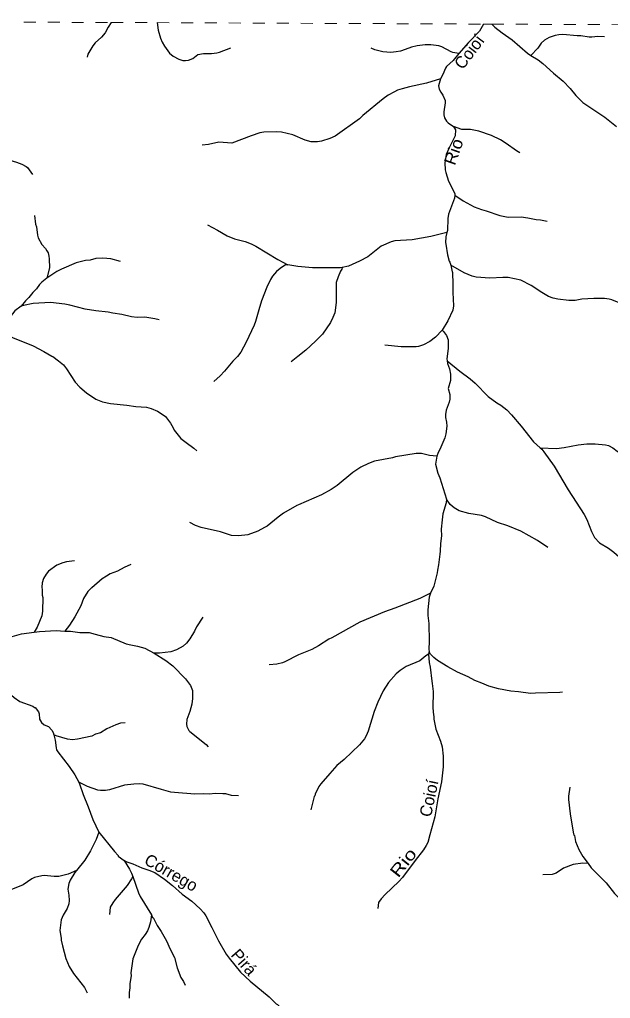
# Model space of a CAD drawing. Extents: x 551.6 to 577.6, y 7567 to 7594.7.
# Drawn here: x 563.65 to 568.58, y 7586.53 to 7594.71 of the extents above; entities that cross this region are included whole.
import ezdxf
from ezdxf.enums import TextEntityAlignment as Align

# ---------------------------------------------------------------- set-up
doc = ezdxf.new("R2010")
doc.units = 0
doc.header["$LTSCALE"] = 0.04
doc.linetypes.add('SHORT_DASHED', pattern=[2.7, 1.5, -1.2])
doc.layers.add('53', color=7, linetype='SHORT_DASHED', lineweight=13)
doc.layers.add('7', color=7, linetype='Continuous', lineweight=25)
doc.layers.add('61', color=7, linetype='Continuous')

msp = doc.modelspace()

# ---------------------------------------------------------------- linework, layer by layer
at = {"layer": '53'}
msp.add_lwpolyline([(557.7663, 7594.7075), (559.9893, 7594.6994), (560.513, 7594.6975), (560.888, 7594.6961), (564.4189, 7594.6832), (564.8007, 7594.6818), (567.5244, 7594.6698), (567.5959, 7594.6695), (570.5848, 7594.6561)], dxfattribs=at)
at = {"layer": '7'}
for points in [[(564.4189, 7594.6832), (564.3936, 7594.6439), (564.3687, 7594.5972), (564.3365, 7594.5602), (564.2842, 7594.5143), (564.2649, 7594.4878), (564.2238, 7594.4185), (564.2166, 7594.3936)], [(564.8007, 7594.6818), (564.8105, 7594.6198), (564.8298, 7594.5522), (564.8443, 7594.5184), (564.8636, 7594.4846), (564.9039, 7594.4282), (564.9361, 7594.4016), (564.9828, 7594.3775), (565.0166, 7594.367), (565.0391, 7594.3654), (565.0633, 7594.3694), (565.0987, 7594.3823), (565.1421, 7594.4153), (565.1872, 7594.4242), (565.2548, 7594.4242), (565.2999, 7594.4298), (565.3224, 7594.4354), (565.4166, 7594.4717)], [(567.5244, 7594.6698), (567.4929, 7594.6101), (567.3988, 7594.5159), (567.3198, 7594.4245)], [(567.5959, 7594.6695), (567.6193, 7594.6455), (567.6813, 7594.5964), (567.765, 7594.5393), (567.8921, 7594.4258), (567.9199, 7594.4085)], [(568.5344, 7594.5634), (568.4788, 7594.565), (568.4289, 7594.5602), (568.4064, 7594.561), (568.3388, 7594.5715), (568.3066, 7594.5707), (568.1875, 7594.5835), (568.1537, 7594.5811), (568.1231, 7594.5739), (568.0748, 7594.5578), (568.0346, 7594.5368), (568.008, 7594.5103), (567.9782, 7594.4692), (567.9199, 7594.4085)], [(567.3198, 7594.4245), (567.2684, 7594.4322), (567.2555, 7594.437), (567.1783, 7594.4789), (567.1525, 7594.4869), (567.0865, 7594.4974), (567.0398, 7594.4974), (566.9722, 7594.4894), (566.924, 7594.4773), (566.8724, 7594.4564), (566.8338, 7594.4451), (566.7968, 7594.437), (566.7517, 7594.4338), (566.6841, 7594.4371), (566.6197, 7594.454), (566.5883, 7594.4701)], [(567.3198, 7594.4245), (567.2716, 7594.3662), (567.2161, 7594.3155), (567.208, 7594.3027), (567.1871, 7594.2487), (567.1654, 7594.2131)], [(567.9199, 7594.4085), (567.9815, 7594.3703), (568.0201, 7594.3405), (568.1102, 7594.2592), (568.1915, 7594.1932), (568.2494, 7594.1329), (568.2961, 7594.0733), (568.3549, 7594.0161), (568.5392, 7593.8922), (568.6349, 7593.8141)], [(567.1654, 7594.2131), (567.0495, 7594.1771), (566.9079, 7594.1473), (566.8451, 7594.1304), (566.8064, 7594.1175), (566.7815, 7594.1055), (566.7308, 7594.0765), (566.6865, 7594.0459), (566.5183, 7593.9067), (566.4894, 7593.8793), (566.2882, 7593.7345), (566.2415, 7593.7135), (566.1739, 7593.691), (566.1385, 7593.6854), (566.087, 7593.6854)], [(567.1654, 7594.2131), (567.1501, 7594.153), (567.1557, 7594.1272), (567.1686, 7594.1015), (567.1863, 7594.0757), (567.2056, 7594.0314), (567.2056, 7594.0129), (567.1943, 7593.9373), (567.1943, 7593.9131), (567.2008, 7593.8874), (567.2177, 7593.8584), (567.2298, 7593.8447), (567.2744, 7593.8145)], [(563.1116, 7593.9131), (563.1172, 7593.8793), (563.1172, 7593.7844), (563.1221, 7593.7618), (563.1454, 7593.7176), (563.1824, 7593.6669), (563.2227, 7593.6298), (563.2637, 7593.6073), (563.3426, 7593.5799), (563.3764, 7593.5719), (563.4472, 7593.5638), (563.5261, 7593.5477), (563.6275, 7593.518), (563.6726, 7593.5003), (563.708, 7593.4818), (563.7192, 7593.4713), (563.7619, 7593.4134)], [(567.2744, 7593.8145), (567.2909, 7593.786), (567.2877, 7593.7361), (567.2386, 7593.6379)], [(567.8293, 7593.5952), (567.8012, 7593.6105), (567.7159, 7593.6741), (567.666, 7593.7031), (567.5911, 7593.7401), (567.4857, 7593.7771), (567.4181, 7593.7892), (567.344, 7593.7892), (567.2744, 7593.8145)], [(566.087, 7593.6854), (566.0355, 7593.7007), (565.934, 7593.7441), (565.8391, 7593.7667), (565.8005, 7593.7715), (565.691, 7593.7667), (565.6572, 7593.761), (565.5864, 7593.7377), (565.4254, 7593.6765), (565.3152, 7593.6838), (565.2307, 7593.6652), (565.1783, 7593.6588)], [(567.2386, 7593.6379), (567.2137, 7593.5816), (567.2024, 7593.5107), (567.2064, 7593.4528), (567.2104, 7593.4303), (567.233, 7593.3594), (567.2853, 7593.2564), (567.286, 7593.2416)], [(567.286, 7593.2416), (567.2845, 7593.2162), (567.233, 7593.0826), (567.2281, 7593.0472), (567.2249, 7592.9474), (567.2201, 7592.9295)], [(567.286, 7593.2416), (567.3569, 7593.1936), (567.4471, 7593.1453), (567.5082, 7593.1204), (567.5485, 7593.1099), (567.6611, 7593.0705), (567.7304, 7593.0568), (567.8398, 7593.06), (567.8961, 7593.0528), (567.9638, 7593.0383), (568.0024, 7593.0359), (568.0579, 7593.023)], [(563.7772, 7593.0721), (563.786, 7592.9989), (563.7933, 7592.9764), (563.8029, 7592.9088), (563.8094, 7592.8862), (563.8391, 7592.8291), (563.8697, 7592.7961), (563.8818, 7592.7768), (563.8914, 7592.7591), (563.8979, 7592.7333), (563.9011, 7592.7108), (563.9027, 7592.6335), (563.8815, 7592.5493)], [(565.221, 7592.9933), (565.3047, 7592.9498), (565.3852, 7592.9031), (565.4479, 7592.8781), (565.5349, 7592.8556), (565.5864, 7592.8363), (565.625, 7592.8162), (565.8085, 7592.7051), (565.8932, 7592.6603)], [(567.2201, 7592.9295), (567.0865, 7592.8975), (566.9288, 7592.8693), (566.7839, 7592.8588), (566.7549, 7592.8524), (566.672, 7592.8154), (566.5602, 7592.726), (566.4902, 7592.689), (566.3992, 7592.6496), (566.346, 7592.6366), (566.3316, 7592.6343)], [(567.2201, 7592.9295), (567.2104, 7592.8927), (567.2072, 7592.846), (567.212, 7592.8331), (567.2249, 7592.743), (567.2386, 7592.6906), (567.2442, 7592.6834), (567.2526, 7592.6566)], [(564.4959, 7592.6874), (564.4162, 7592.7108), (564.347, 7592.7148), (564.2906, 7592.7116), (564.2424, 7592.6995), (564.2037, 7592.6963), (564.1265, 7592.6753), (564.0025, 7592.6238), (563.9639, 7592.6045), (563.8815, 7592.5493)], [(565.8932, 7592.6603), (565.8737, 7592.6608), (565.8278, 7592.6287), (565.798, 7592.6029), (565.7642, 7592.5643), (565.7473, 7592.5369), (565.7159, 7592.4726), (565.6733, 7592.3583), (565.6515, 7592.2842)], [(566.3316, 7592.6343), (566.0982, 7592.6335), (565.9743, 7592.6448), (565.8932, 7592.6603)], [(567.2526, 7592.6566), (567.2627, 7592.6013), (567.2652, 7592.5997), (567.2652, 7592.5579), (567.27, 7592.5369), (567.27, 7592.5192)], [(568.0112, 7592.4275), (567.9243, 7592.4862), (567.8366, 7592.5313), (567.732, 7592.5546), (567.6869, 7592.5546), (567.5791, 7592.5474), (567.4648, 7592.5562), (567.431, 7592.5643), (567.3626, 7592.5916), (567.2526, 7592.6566)], [(566.346, 7592.6366), (566.3429, 7592.6238), (566.3324, 7592.6078), (566.3123, 7592.5595), (566.2962, 7592.5128), (566.2962, 7592.3454), (566.2833, 7592.2601), (566.2688, 7592.2198), (566.2487, 7592.1796), (566.1811, 7592.0822), (566.1224, 7592.0218), (566.0411, 7591.9462), (565.9759, 7591.8939), (565.9188, 7591.8488)], [(563.8815, 7592.5493), (563.8383, 7592.5152), (563.819, 7592.4951), (563.7933, 7592.4597), (563.7627, 7592.4275), (563.7313, 7592.388)], [(567.27, 7592.5192), (567.27, 7592.4291), (567.2748, 7592.3164), (567.2692, 7592.2826), (567.2289, 7592.1909), (567.179, 7592.1138)], [(569.0084, 7591.9599), (568.94, 7592.0259), (568.9118, 7592.0605), (568.8635, 7592.1297), (568.8289, 7592.1973), (568.7959, 7592.24), (568.7195, 7592.3092), (568.6865, 7592.3301), (568.5963, 7592.3663), (568.5754, 7592.3727), (568.5352, 7592.3776), (568.4466, 7592.3792), (568.3468, 7592.3719), (568.2905, 7592.3631), (568.2374, 7592.3631), (568.1456, 7592.3743), (568.107, 7592.3824), (568.0684, 7592.3961), (568.0112, 7592.4275)], [(563.7313, 7592.388), (563.7031, 7592.3599), (563.6652, 7592.314)], [(564.0717, 7592.3228), (564.0315, 7592.3325), (563.9124, 7592.3454), (563.7659, 7592.3373), (563.6854, 7592.3212), (563.6652, 7592.314)], [(564.8178, 7592.2005), (564.7832, 7592.2094), (564.6979, 7592.2239), (564.6351, 7592.2206), (564.5868, 7592.2255), (564.5063, 7592.244), (564.4323, 7592.2552), (564.3937, 7592.2657), (564.289, 7592.2762), (564.2013, 7592.2898), (564.0717, 7592.3228)], [(563.6652, 7592.314), (563.6146, 7592.2746), (563.5623, 7592.2126), (563.5406, 7592.1957), (563.4939, 7592.1651), (563.4193, 7592.1239)], [(565.6515, 7592.2842), (565.6234, 7592.186), (565.6113, 7592.1571), (565.5453, 7592.0154), (565.501, 7591.9317), (565.4729, 7591.8955), (565.4335, 7591.8553), (565.3634, 7591.7708), (565.3272, 7591.7321), (565.2749, 7591.6863)], [(563.4193, 7592.1239), (563.7659, 7591.9824), (563.8569, 7591.9365), (563.922, 7591.8963)], [(567.179, 7592.1138), (567.1252, 7592.0564), (567.0777, 7592.0194), (567.0254, 7591.9913), (566.9819, 7591.9784), (566.9626, 7591.9744), (566.837, 7591.9744), (566.7026, 7591.9881)], [(567.179, 7592.1138), (567.1919, 7592.1023), (567.2177, 7592.0685), (567.2314, 7592.0331), (567.2298, 7591.9607), (567.2201, 7591.8738), (567.2233, 7591.8576)], [(563.922, 7591.8963), (563.9317, 7591.8931), (563.9784, 7591.8593), (564.0186, 7591.8239), (564.046, 7591.7917), (564.1184, 7591.6806), (564.1562, 7591.638), (564.211, 7591.5913), (564.289, 7591.539), (564.3454, 7591.5172), (564.413, 7591.5011), (564.5482, 7591.4875), (564.6222, 7591.4762), (564.7124, 7591.4722), (564.751, 7591.4601)], [(567.2233, 7591.8576), (567.2249, 7591.8352), (567.241, 7591.7901), (567.2507, 7591.7482), (567.2491, 7591.6951), (567.2298, 7591.6275), (567.2442, 7591.576), (567.2434, 7591.5374), (567.2378, 7591.5132), (567.2137, 7591.4456)], [(567.2233, 7591.8576), (567.3272, 7591.7732), (567.4149, 7591.708), (567.4551, 7591.6718), (567.563, 7591.5607), (567.6354, 7591.5076), (567.6692, 7591.4875), (567.7207, 7591.448), (567.7593, 7591.407), (567.839, 7591.312), (567.9428, 7591.1832), (567.9974, 7591.1312)], [(564.751, 7591.4601), (564.8033, 7591.4376), (564.8516, 7591.4086), (564.8701, 7591.3925), (564.9127, 7591.3378), (564.9353, 7591.2975), (564.9421, 7591.2791), (564.9997, 7591.2106), (565.0423, 7591.1752), (565.1075, 7591.1285), (565.1317, 7591.1068)], [(567.2137, 7591.4456), (567.2072, 7591.4102), (567.2072, 7591.3845), (567.2153, 7591.3474), (567.2185, 7591.312), (567.212, 7591.2493), (567.2032, 7591.2155), (567.1702, 7591.1366), (567.1444, 7591.0851), (567.1368, 7591.0621)], [(567.9974, 7591.1312), (568.1344, 7591.1253), (568.1988, 7591.1333), (568.3146, 7591.1559), (568.3871, 7591.1639), (568.4579, 7591.1655), (568.5448, 7591.1575), (568.5698, 7591.1519), (568.6036, 7591.1325), (568.6406, 7591.1028), (568.7404, 7591.0102), (568.7879, 7590.9772), (568.8329, 7590.9539)], [(567.9974, 7591.1312), (568.012, 7591.1205), (568.0297, 7591.0996), (568.115, 7590.9796)], [(567.1368, 7591.0621), (567.0753, 7591.0665), (567.0076, 7591.0834), (566.9626, 7591.0842), (566.792, 7591.0561), (566.7662, 7591.048), (566.6157, 7591.0199), (566.565, 7591.0006), (566.5022, 7590.9708), (566.4354, 7590.9257), (566.3026, 7590.8187), (566.2527, 7590.7849), (566.1723, 7590.7406), (565.9807, 7590.6561)], [(567.1368, 7591.0621), (567.1243, 7590.9949), (567.1444, 7590.9209), (567.1597, 7590.8823), (567.2169, 7590.702)], [(568.115, 7590.9796), (568.2333, 7590.7801), (568.3653, 7590.5764), (568.3879, 7590.533), (568.4257, 7590.4332), (568.4514, 7590.3833), (568.4949, 7590.3382), (568.5673, 7590.2939), (568.614, 7590.2601), (568.7235, 7590.162)], [(567.2169, 7590.702), (567.2128, 7590.673), (567.1863, 7590.5813), (567.179, 7590.5298), (567.1726, 7590.4541), (567.1734, 7590.3962), (567.167, 7590.3334), (567.1646, 7590.269), (567.1597, 7590.2433)], [(568.0627, 7590.3004), (567.9766, 7590.3575), (567.8382, 7590.4372), (567.7271, 7590.4799), (567.6418, 7590.508), (567.542, 7590.5555), (567.5098, 7590.5676), (567.4036, 7590.5845), (567.3215, 7590.607), (567.2797, 7590.6312), (567.2467, 7590.6585), (567.2169, 7590.702)], [(565.9807, 7590.6561), (565.9678, 7590.6513), (565.8567, 7590.5861), (565.8109, 7590.5531), (565.7192, 7590.479), (565.6974, 7590.4654), (565.6427, 7590.4348), (565.5574, 7590.4058), (565.4801, 7590.3978), (565.4222, 7590.401), (565.3304, 7590.43), (565.1679, 7590.4654), (565.1228, 7590.4823), (565.0737, 7590.5072)], [(567.1597, 7590.2433), (567.1509, 7590.1563), (567.1412, 7590.1113), (567.1396, 7590.0887), (567.1114, 7589.9761), (567.0839, 7589.9171)], [(564.1112, 7590.1885), (564.046, 7590.1813), (564.0138, 7590.1724), (563.9639, 7590.1515), (563.8947, 7590.1024), (563.8754, 7590.0775), (563.8528, 7590.0396), (563.8415, 7590.0058), (563.8383, 7589.9696), (563.8415, 7589.9455), (563.8415, 7589.902), (563.8464, 7589.8827), (563.8448, 7589.7668), (563.8383, 7589.7282), (563.8013, 7589.6332), (563.7757, 7589.5914)], [(564.5828, 7590.1587), (564.5273, 7590.1338), (564.4693, 7590.1032), (564.4089, 7590.0799), (564.3792, 7590.0614), (564.3429, 7590.038), (564.2568, 7589.9624), (564.2536, 7589.9624), (564.223, 7589.9326), (564.186, 7589.8731), (564.1635, 7589.8119), (564.1152, 7589.7217), (564.0701, 7589.6509), (564.0298, 7589.6016)], [(567.0839, 7589.9171), (566.9932, 7589.873), (566.7855, 7589.7926), (566.6994, 7589.7636), (566.4926, 7589.6759), (566.2592, 7589.5463)], [(567.0839, 7589.9171), (567.0728, 7589.8843), (567.0607, 7589.7797), (567.0607, 7589.7314), (567.0688, 7589.6638), (567.072, 7589.5141), (567.068, 7589.4513), (567.0712, 7589.4272), (567.0676, 7589.4099)], [(565.1816, 7589.7177), (565.1292, 7589.6364), (565.1139, 7589.601), (565.0745, 7589.5358), (565.0471, 7589.5012), (565.0198, 7589.4763), (564.9635, 7589.4457), (564.9168, 7589.4288), (564.8202, 7589.4167), (564.7759, 7589.4175)], [(563.3765, 7589.4781), (563.3957, 7589.4819), (563.4923, 7589.5318), (563.5422, 7589.5487), (563.5921, 7589.5567), (563.6693, 7589.5785), (563.7757, 7589.5914)], [(563.7757, 7589.5914), (563.8206, 7589.5994), (563.9591, 7589.6074), (564.0298, 7589.6016)], [(564.0298, 7589.6016), (564.0782, 7589.6002), (564.1554, 7589.5906), (564.2327, 7589.5897), (564.2834, 7589.5769)], [(564.2834, 7589.5769), (564.3566, 7589.5575), (564.4178, 7589.5495), (564.5434, 7589.4956), (564.5804, 7589.4859), (564.6367, 7589.4771), (564.6995, 7589.4602), (564.7759, 7589.4175)], [(566.2592, 7589.5463), (566.235, 7589.5342), (566.1489, 7589.4787), (566.0934, 7589.4489), (565.9807, 7589.4038), (565.8681, 7589.3451), (565.8487, 7589.337), (565.8005, 7589.3242), (565.7369, 7589.321)], [(564.7759, 7589.4175), (564.8749, 7589.3571), (564.9321, 7589.3121), (565.0391, 7589.2035), (565.0785, 7589.1487), (565.097, 7589.1053)], [(567.0676, 7589.4099), (567.0439, 7589.395), (566.9932, 7589.3539), (566.8805, 7589.3056), (566.8306, 7589.2735), (566.796, 7589.2437), (566.7324, 7589.1721), (566.6881, 7589.1021), (566.6439, 7589.0071), (566.6141, 7588.9298), (566.5618, 7588.7656), (566.5465, 7588.727), (566.532, 7588.7013), (566.4909, 7588.6514), (566.3614, 7588.5298), (566.301, 7588.4791), (566.2439, 7588.4139)], [(567.0676, 7589.4099), (567.0728, 7589.3403), (567.0801, 7589.3016), (567.0929, 7589.1825), (567.0978, 7589.1648), (567.1042, 7589.0972)], [(567.1412, 7589.3563), (567.1106, 7589.3813), (567.0825, 7589.4103), (567.0712, 7589.4272)], [(568.1851, 7589.0924), (568.1617, 7589.0892), (567.9605, 7589.0843), (567.9187, 7589.0803), (567.8173, 7589.0956), (567.7545, 7589.1004), (567.6515, 7589.1189), (567.571, 7589.1415), (567.5123, 7589.168), (567.4535, 7589.189), (567.3964, 7589.2203), (567.3086, 7589.259), (567.2266, 7589.3024), (567.1412, 7589.3563)], [(563.5245, 7589.1552), (563.5647, 7589.0859), (563.6066, 7589.0473), (563.6565, 7589.0151), (563.7627, 7588.9741), (563.7772, 7588.9636), (563.7828, 7588.9628), (563.811, 7588.9282), (563.8174, 7588.9105), (563.8206, 7588.8671), (563.8367, 7588.8397), (563.8585, 7588.8195), (563.8939, 7588.8043), (563.9228, 7588.7737), (563.9333, 7588.7544), (563.9382, 7588.7363)], [(565.097, 7589.1053), (565.0978, 7589.0393), (565.0906, 7588.991), (565.0737, 7588.9298), (565.0504, 7588.8622), (565.0471, 7588.8236), (565.0487, 7588.8043), (565.0657, 7588.7729), (565.0745, 7588.7632), (565.2105, 7588.6546), (565.2266, 7588.6361)], [(567.1042, 7589.0972), (567.1026, 7588.9604), (567.1074, 7588.9009), (567.1106, 7588.8936), (567.1106, 7588.8671), (567.1267, 7588.7834), (567.1662, 7588.6819), (567.1799, 7588.6353), (567.1879, 7588.5564), (567.1895, 7588.4695), (567.1742, 7588.3423), (567.1444, 7588.2023), (567.1187, 7588.051), (567.0785, 7587.9013)], [(564.5345, 7588.8365), (564.4951, 7588.8324), (564.4564, 7588.8187), (564.3808, 7588.7866), (564.3277, 7588.7527), (564.2874, 7588.7399), (564.2552, 7588.7254), (564.1361, 7588.6996), (564.0943, 7588.6948), (564.054, 7588.698), (563.9575, 7588.7262), (563.9382, 7588.7363)], [(563.9382, 7588.7363), (563.9502, 7588.6916), (563.9574, 7588.6272), (563.9623, 7588.6111), (563.9727, 7588.5934)], [(563.9727, 7588.5934), (564.0677, 7588.4711), (564.1152, 7588.4027), (564.147, 7588.3414)], [(566.2439, 7588.4139), (566.1666, 7588.3262), (566.1513, 7588.3037), (566.1207, 7588.2409), (566.1175, 7588.2256), (566.1127, 7588.22), (566.0853, 7588.1097)], [(564.147, 7588.3414), (564.1538, 7588.3278), (564.1828, 7588.2361), (564.227, 7588.1331), (564.2641, 7588.0284), (564.3137, 7587.9215), (564.4443, 7587.7604)], [(564.6061, 7588.3246), (564.5289, 7588.3149), (564.4033, 7588.2763), (564.3695, 7588.2699), (564.3293, 7588.2699), (564.3051, 7588.2747), (564.2214, 7588.3037), (564.147, 7588.3414)], [(565.4793, 7588.2264), (565.4222, 7588.2304), (565.3755, 7588.2417), (565.3498, 7588.2441), (565.2854, 7588.2449), (565.2371, 7588.2409), (565.192, 7588.2441), (565.1164, 7588.2393), (564.9474, 7588.253), (564.9152, 7588.2578), (564.8379, 7588.2779), (564.6834, 7588.323), (564.6544, 7588.327), (564.6061, 7588.3246)], [(568.2454, 7588.2981), (568.235, 7588.2248), (568.235, 7588.1958), (568.2486, 7588.0767), (568.2736, 7587.9222), (568.28, 7587.8973), (568.284, 7587.8949), (568.2945, 7587.845), (568.3203, 7587.7774), (568.3557, 7587.7186), (568.3989, 7587.6606)], [(564.3137, 7587.9215), (564.2914, 7587.8627), (564.2447, 7587.7661), (564.1989, 7587.6904), (564.1276, 7587.6019)], [(567.0785, 7587.9013), (567.0599, 7587.8369), (567.0479, 7587.8112), (567.0245, 7587.7741), (566.9537, 7587.6872), (566.8491, 7587.5448), (566.8177, 7587.5101), (566.7034, 7587.4031), (566.672, 7587.3669), (566.6503, 7587.3355), (566.6423, 7587.2856)], [(564.4443, 7587.7604), (564.4757, 7587.7274), (564.4757, 7587.7231), (564.5249, 7587.6874)], [(564.5249, 7587.6874), (564.5482, 7587.6751), (564.5981, 7587.6582), (564.6737, 7587.626), (564.7325, 7587.6067), (564.7808, 7587.5858), (564.8628, 7587.5303), (564.9296, 7587.478), (565.0093, 7587.4063), (565.0914, 7587.346), (565.1614, 7587.2824), (565.1912, 7587.2494), (565.2089, 7587.2236), (565.2572, 7587.1271)], [(564.5249, 7587.6874), (564.5707, 7587.6148), (564.5876, 7587.581), (564.5976, 7587.5527)], [(568.3989, 7587.6606), (568.3549, 7587.6631), (568.2744, 7587.6534), (568.1939, 7587.6228), (568.1312, 7587.581), (568.0973, 7587.5681), (568.0209, 7587.5665)], [(564.1276, 7587.6019), (564.0589, 7587.5729), (563.9816, 7587.5528), (563.943, 7587.552), (563.8593, 7587.56), (563.84, 7587.5584), (563.7788, 7587.5431), (563.7546, 7587.5319), (563.6838, 7587.4836), (563.5792, 7587.4401), (563.5422, 7587.4128), (563.5237, 7587.3902)], [(564.1276, 7587.6019), (564.1152, 7587.5866), (564.0765, 7587.523), (564.0637, 7587.4941), (564.0556, 7587.4458), (564.0653, 7587.3975), (564.0669, 7587.3524), (564.0637, 7587.3251), (564.05, 7587.2864), (564.017, 7587.2285), (564.0009, 7587.1898), (563.9896, 7587.1029), (564.0009, 7587.0385)], [(568.3989, 7587.6606), (568.4247, 7587.626), (568.5488, 7587.5005), (568.6196, 7587.4104), (568.6518, 7587.3774), (568.7162, 7587.321), (568.7911, 7587.2615)], [(564.5976, 7587.5527), (564.5884, 7587.5327), (564.5522, 7587.4771), (564.45, 7587.3597), (564.4307, 7587.3315), (564.4097, 7587.2961), (564.4033, 7587.2357)], [(564.5976, 7587.5527), (564.6463, 7587.4152), (564.6608, 7587.3862), (564.755, 7587.2317)], [(564.755, 7587.2317), (564.7461, 7587.1754), (564.7317, 7587.1271), (564.7196, 7587.0981), (564.7027, 7587.0691), (564.6721, 7587.0289), (564.6431, 7586.9774), (564.5997, 7586.8647), (564.582, 7586.7472), (564.5836, 7586.7231), (564.5747, 7586.6587), (564.5747, 7586.6233), (564.5691, 7586.5846), (564.5691, 7586.5372)], [(564.755, 7587.2317), (564.763, 7587.2116), (564.7671, 7587.2108), (564.8025, 7587.144), (564.8355, 7587.0949), (564.8805, 7587.0144), (564.9111, 7586.9452), (564.9457, 7586.8776), (564.9683, 7586.7907)], [(565.2572, 7587.1271), (565.3135, 7587.0152), (565.3787, 7586.9049), (565.4029, 7586.8695), (565.4978, 7586.7528), (565.5767, 7586.6796), (565.7377, 7586.5484), (565.7956, 7586.4897), (565.8061, 7586.4832), (565.8584, 7586.4349), (565.9002, 7586.4003), (565.93, 7586.3802)], [(564.0009, 7587.0385), (564.0009, 7587.0224), (564.0106, 7586.9742), (564.0379, 7586.8679), (564.0669, 7586.8019), (564.1031, 7586.744), (564.1957, 7586.6249), (564.2182, 7586.5822)], [(564.9683, 7586.7907), (564.9989, 7586.7102), (565.0206, 7586.6772), (565.0351, 7586.6466)]]:
    msp.add_lwpolyline(points, dxfattribs=at)

# ---------------------------------------------------------------- texts
at = {"layer": '61'}
for s, rotation, p in [('Coioí', 52.925, (567.4465, 7594.4076)), ('Coioí', 78.179, (567.119, 7588.1962)), ('Córrego', 330.136, (564.894, 7587.5422)), ('Pirá', 311.159, (565.4887, 7586.8044))]:
    msp.add_text(s, height=0.1, rotation=rotation, dxfattribs=at).set_placement(p, align=Align.CENTER)
for rotation, width, p in [(70.516, 1.1, (567.3232, 7593.5875)), (51.668, 1.3, (566.8946, 7587.638))]:
    msp.add_text('Rio', height=0.1, rotation=rotation, dxfattribs=dict(at, width=width)).set_placement(p, align=Align.CENTER)

doc.saveas('drawing.dxf')
